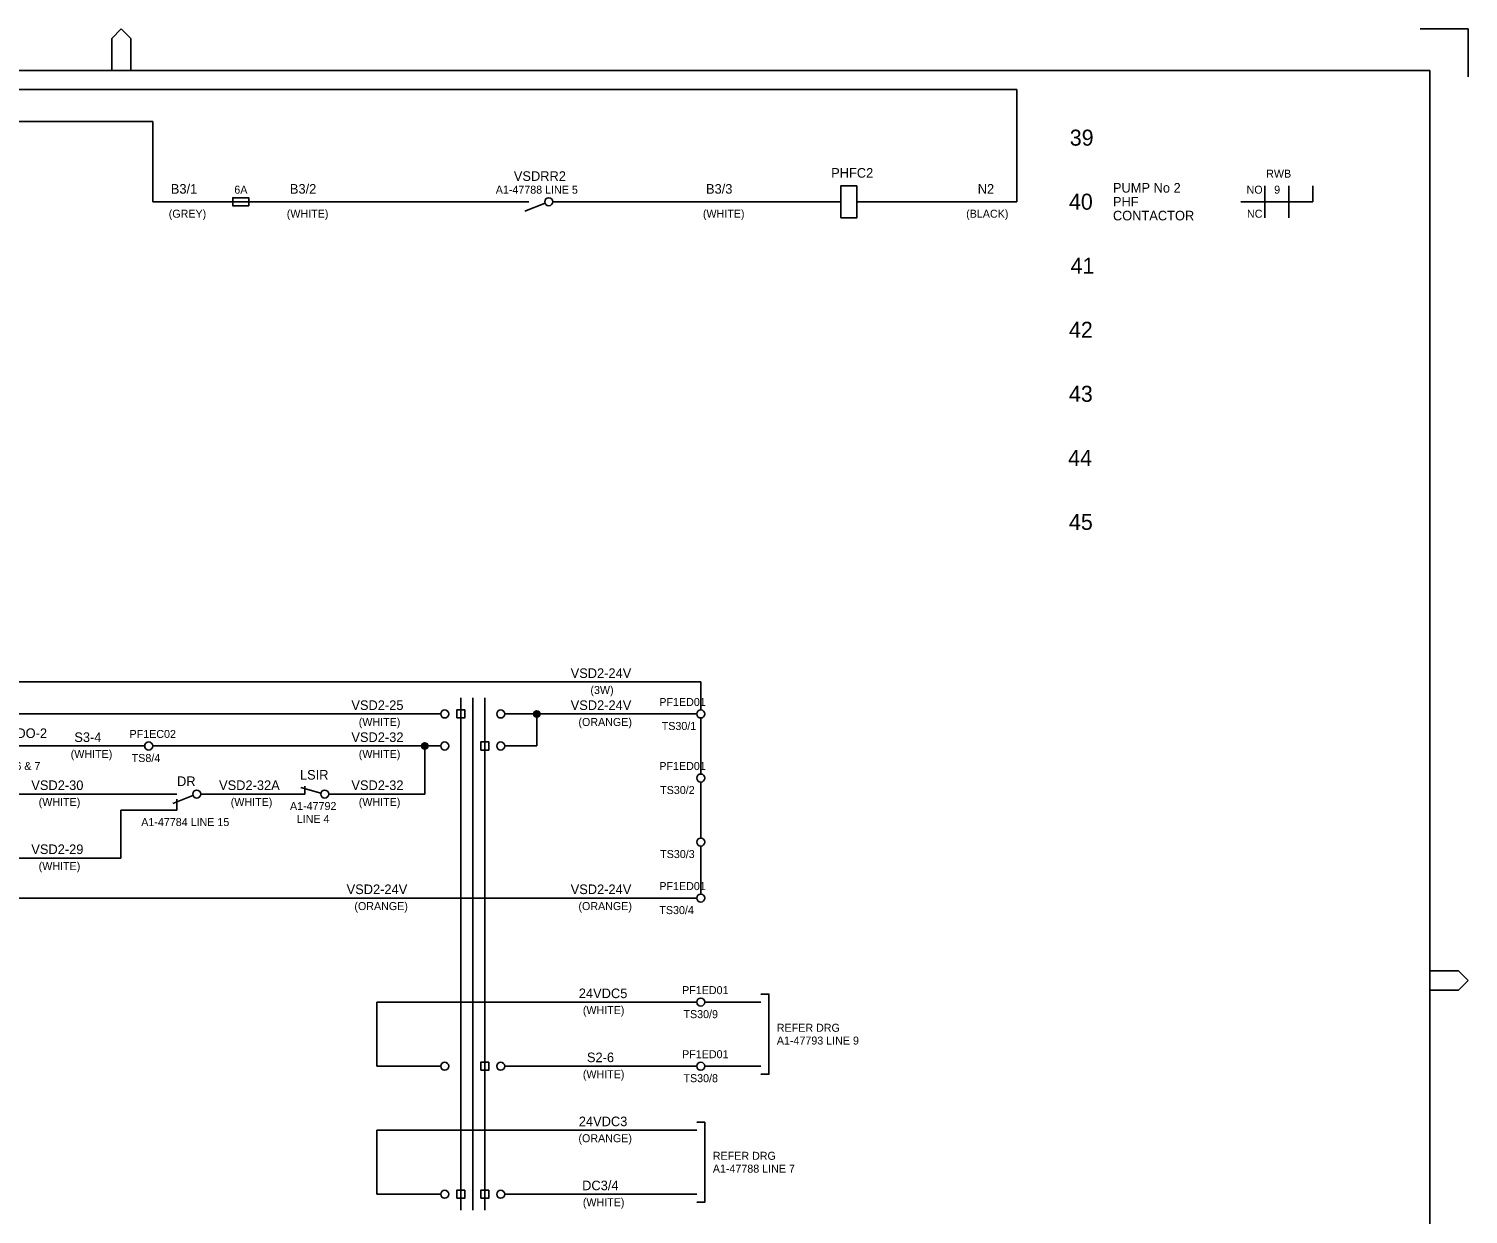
# Model space of a CAD drawing. Extents: x 0 to 841, y 0 to 594.
# Drawn here: x 391.3 to 841, y 223.8 to 594 of the extents above; entities that cross this region are included whole.
import ezdxf

# ---------------------------------------------------------------- set-up
doc = ezdxf.new("R2010")
doc.units = 0
for name, color, linetype in [('A1BORDER', 7, 'Continuous'), ('Level 1', 7, 'Continuous'), ('Level 10', 7, 'Continuous'), ('Level 5', 7, 'Continuous'), ('Level 6', 7, 'Continuous')]:
    doc.layers.add(name, color=color, linetype=linetype)

msp = doc.modelspace()

# ---------------------------------------------------------------- linework, layer by layer
at = {"layer": 'A1BORDER'}
for p, q in [((417.19, 591), (420.19, 594)), ((423.19, 591), (420.19, 594)), ((826, 594), (841, 594)), ((841, 579), (841, 594)), ((417.19, 581), (417.19, 591)), ((423.19, 581), (423.19, 591)), ((28, 581), (829, 581)), ((829, 581), (829, 15)), ((829, 299.76), (838, 299.76)), ((838, 299.76), (841, 296.76)), ((829, 293.76), (838, 293.76)), ((838, 293.76), (841, 296.76))]:
    msp.add_line(p, q, dxfattribs=at)
at = {"layer": 'Level 1'}
for p, q in [((57.5, 575), (700, 575)), ((700, 575), (700, 540)), ((130, 565), (430, 565)), ((430, 565), (430, 540)), ((777.5, 535), (777.5, 545)), ((785, 535), (785, 545)), ((792.5, 540), (792.5, 545)), ((430, 540), (545, 540)), ((547.5, 540), (545, 540)), ((545, 540), (545, 540)), ((555, 540), (555, 540)), ((645, 540), (630, 540)), ((700, 540), (650, 540)), ((770, 540), (792.5, 540)), ((601.25, 381.25), (601.25, 390)), ((526.25, 385), (526.25, 225)), ((530, 385), (530, 225)), ((533.75, 385), (533.75, 225)), ((550, 370), (550, 380)), ((601.25, 361.25), (601.25, 378.75)), ((427.5, 370), (385, 370)), ((515, 370), (515, 355)), ((601.25, 341.25), (601.25, 358.75)), ((477.5, 355), (475, 355)), ((485, 355), (515, 355)), ((435, 350), (420, 350)), ((420, 335), (420, 350)), ((601.25, 323.75), (601.25, 338.75)), ((600, 322.5), (325, 322.5)), ((500, 270), (500, 290)), ((602.5, 290), (620, 290)), ((520, 270), (500, 270)), ((602.5, 270), (620, 270)), ((500, 230), (500, 250)), ((520, 230), (500, 230))]:
    msp.add_line(p, q, dxfattribs=at)
for points in [[(525, 378.75), (527.5, 378.75), (527.5, 381.25), (525, 381.25)], [(532.5, 368.75), (535, 368.75), (535, 371.25), (532.5, 371.25)], [(532.5, 268.75), (535, 268.75), (535, 271.25), (532.5, 271.25)], [(525, 228.75), (527.5, 228.75), (527.5, 231.25), (525, 231.25)], [(532.5, 228.75), (535, 228.75), (535, 231.25), (532.5, 231.25)]]:
    msp.add_lwpolyline(points, close=True, dxfattribs=at)
for points in [[(620, 292.5), (622.5, 292.5), (622.5, 267.5), (620, 267.5)], [(600, 252.5), (602.5, 252.5), (602.5, 227.5), (600, 227.5)]]:
    msp.add_lwpolyline(points, dxfattribs=at)
at = {"layer": 'Level 10'}
for p, q in [((552.59, 539.54), (546.25, 537)), ((549, 380), (549, 380)), ((549.1, 379.56), (549.1, 380.44)), ((549.4, 379.2), (549.4, 380.8)), ((549.7, 379.05), (549.7, 380.95)), ((550, 379), (550, 380.99)), ((550.3, 379.05), (550.3, 380.95)), ((550.6, 379.2), (550.6, 380.8)), ((550.9, 379.56), (550.9, 380.44)), ((514, 370), (514, 370)), ((514.1, 369.56), (514.1, 370.44)), ((514.4, 369.2), (514.4, 370.8)), ((514.7, 369.05), (514.7, 370.95)), ((515, 369), (515, 370.99)), ((515.3, 369.05), (515.3, 370.95)), ((515.6, 369.2), (515.6, 370.8)), ((515.9, 369.56), (515.9, 370.44)), ((482.54, 355.32), (476.25, 357)), ((477.5, 357.5), (477.5, 355)), ((437.5, 355), (435, 355)), ((442.59, 354.54), (436.25, 352)), ((437.5, 353.37), (437.5, 350)), ((437.5, 350), (435, 350))]:
    msp.add_line(p, q, dxfattribs=at)
for points in [[(650, 545), (650, 535), (645, 535), (645, 545), (650, 545)], [(460, 540), (460, 541.25), (455, 541.25), (455, 538.75), (460, 538.75), (460, 540)]]:
    msp.add_lwpolyline(points, dxfattribs=at)
for centre, radius in [((553.75, 540), 1.25), ((550, 380), 1), ((515, 370), 1), ((443.75, 355), 1.25), ((483.75, 355), 1.25)]:
    msp.add_circle(centre, radius, dxfattribs=at)
at = {"layer": 'Level 5'}
for centre in [(521.25, 380), (538.75, 380), (601.25, 380), (428.75, 370), (521.25, 370), (538.75, 370), (601.25, 360), (601.25, 340), (601.25, 322.5), (601.25, 290), (521.25, 270), (538.75, 270), (601.25, 270), (521.25, 230), (538.75, 230)]:
    msp.add_circle(centre, 1.25, dxfattribs=at)
at = {"layer": 'Level 6'}
for p, q in [((555, 540), (645, 540)), ((142.5, 390), (601.25, 390)), ((260, 380), (520, 380)), ((540, 380), (600, 380)), ((430, 370), (520, 370)), ((540, 370), (550, 370)), ((325, 355), (435, 355)), ((445, 355), (475, 355)), ((365, 335), (420, 335)), ((500, 290), (600, 290)), ((540, 270), (600, 270)), ((500, 250), (600, 250)), ((540, 230), (600, 230))]:
    msp.add_line(p, q, dxfattribs=at)

# ---------------------------------------------------------------- texts
at = {"layer": 'Level 1'}
for s, height, p in [('39', 5, (716.52, 557.5)), ('RWB', 2.5, (777.89, 547.5)), ('NO', 2.5, (771.76, 542.5)), ('9', 2.5, (780.38, 542.5)), ('40', 5, (716.27, 537.5)), ('NC', 2.5, (771.88, 535)), ('41', 5, (716.77, 517.5)), ('42', 5, (716.27, 497.5)), ('43', 5, (716.27, 477.5)), ('44', 5, (716.02, 457.5)), ('45', 5, (716.27, 437.5)), ('PF1ED01', 2.5, (588.29, 382.5)), ('PF1EC02', 2.5, (422.77, 372.5)), ('PF1ED01', 2.5, (588.29, 362.5)), ('PF1ED01', 2.5, (588.29, 325)), ('PF1ED01', 2.5, (595.4, 292.5)), ('A1-47793 LINE 9', 2.5, (625, 276.75)), ('REFER DRG', 2.5, (625, 280.75)), ('PF1ED01', 2.5, (595.4, 272.5)), ('REFER DRG', 2.5, (605, 240.75)), ('A1-47788 LINE 7', 2.5, (605, 236.75))]:
    msp.add_text(s, height=height, dxfattribs=at).set_placement(p)
at = {"layer": 'Level 5'}
for s, height, p in [('VSDRR2', 3, (542.83, 546.5)), ('PHFC2', 3, (641.97, 547.5)), ('B3/1', 3, (435.67, 542.5)), ('6A', 2.5, (455.51, 542.5)), ('B3/2', 3, (472.87, 542.5)), ('A1-47788 LINE 5', 2.5, (537.18, 542.5)), ('B3/3', 3, (602.87, 542.5)), ('N2', 3, (687.76, 542.5)), ('PUMP No 2', 3, (730, 542.84)), ('PHF', 3, (730, 538.5)), ('(GREY)', 2.5, (435.02, 535)), ('(WHITE)', 2.5, (471.9, 535)), ('(WHITE)', 2.5, (601.9, 535)), ('(BLACK)', 2.5, (684.15, 535)), ('CONTACTOR', 3, (730, 534.16)), ('VSD2-24V', 3, (560.58, 391.25)), ('(3W)', 2.5, (566.76, 386.25)), ('VSD2-25', 3, (492.08, 381.25)), ('VSD2-24V', 3, (560.59, 381.25)), ('(WHITE)', 2.5, (494.39, 376.25)), ('(ORANGE)', 2.5, (563.02, 376.25)), ('RTU SLOT 3 DO-2', 3, (363.12, 372.5)), ('S3-4', 3, (405.52, 371.25)), ('VSD2-32', 3, (492.08, 371.25)), ('TS30/1', 2.5, (589.04, 375)), ('(WHITE)', 2.5, (404.39, 366.25)), ('(WHITE)', 2.5, (494.39, 366.25)), ('A1-47794 LINE 6 & 7', 2.5, (363.32, 362.5)), ('TS8/4', 2.5, (423.45, 365)), ('DR', 3, (437.61, 357.5)), ('LSIR', 3, (476.01, 359.5)), ('VSD2-30', 3, (392.08, 356.25)), ('VSD2-32A', 3, (450.74, 356.25)), ('VSD2-32', 3, (492.08, 356.25)), ('TS30/2', 2.5, (588.55, 355)), ('(WHITE)', 2.5, (394.39, 351.25)), ('(WHITE)', 2.5, (454.39, 351.25)), ('A1-47792', 2.5, (472.9, 350)), ('(WHITE)', 2.5, (494.39, 351.25)), ('A1-47784 LINE 15', 2.5, (426.43, 345)), ('LINE 4', 2.5, (475.02, 346)), ('VSD2-29', 3, (392.08, 336.25)), ('TS30/3', 2.5, (588.55, 335)), ('(WHITE)', 2.5, (394.39, 331.25)), ('VSD2-24V', 3, (490.59, 323.75)), ('VSD2-24V', 3, (560.59, 323.75)), ('(ORANGE)', 2.5, (493.02, 318.75)), ('(ORANGE)', 2.5, (563.02, 318.75)), ('TS30/4', 2.5, (588.3, 317.5)), ('24VDC5', 3, (563.13, 291.25)), ('(WHITE)', 2.5, (564.39, 286.25)), ('TS30/9', 2.5, (595.83, 285)), ('S2-6', 3, (565.67, 271.25)), ('(WHITE)', 2.5, (564.39, 266.25)), ('TS30/8', 2.5, (595.83, 265)), ('24VDC3', 3, (563.13, 251.25)), ('(ORANGE)', 2.5, (563.02, 246.25)), ('DC3/4', 3, (564.17, 231.25)), ('(WHITE)', 2.5, (564.39, 226.25))]:
    msp.add_text(s, height=height, dxfattribs=at).set_placement(p)

doc.saveas('drawing.dxf')
